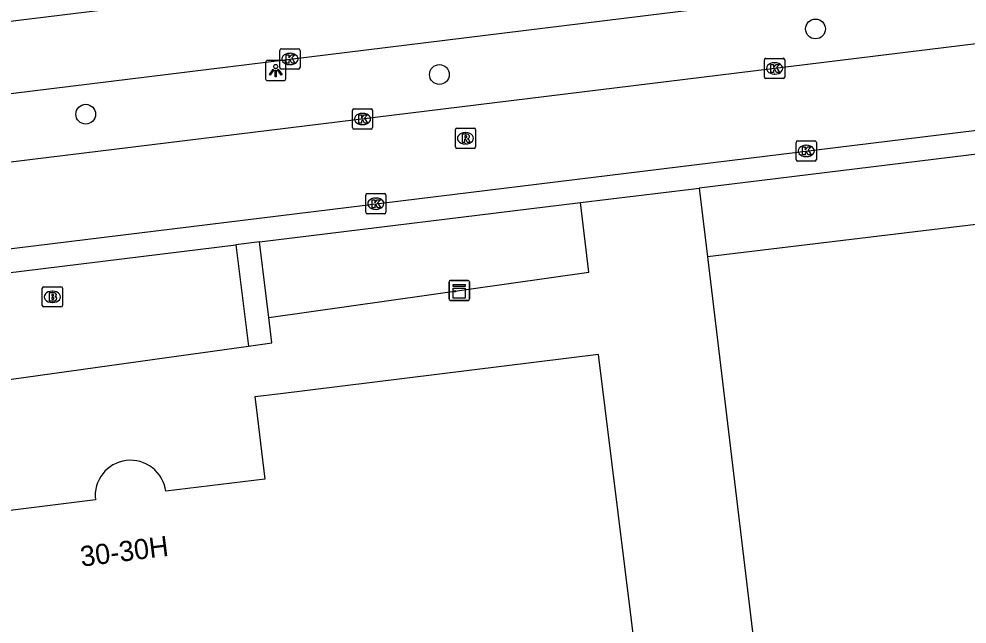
# Model space of a CAD drawing. Extents: x 161477 to 163040, y 383680 to 384868.
# Drawn here: x 162276.62 to 162323.55, y 384039.95 to 384069.9 of the extents above; entities that cross this region are included whole.
import ezdxf

# ---------------------------------------------------------------- set-up
doc = ezdxf.new("R2010")
doc.units = 0
for name, color, linetype in [('IMGEO_Boom', 7, 'Continuous'), ('IMGEO_Brandkraan', 7, 'Continuous'), ('IMGEO_Gemengd_bos', 7, 'Continuous'), ('IMGEO_Groenvoorziening', 7, 'Continuous'), ('IMGEO_Kast', 7, 'Continuous'), ('IMGEO_Kolk', 7, 'Continuous'), ('IMGEO_Lichtpunt', 7, 'Continuous'), ('IMGEO_Pand', 7, 'Continuous'), ('IMGEO_Pand_nummerreeks', 7, 'Continuous'), ('IMGEO_Rijbaan_lokaal_gesloten', 7, 'Continuous'), ('IMGEO_Rioolput', 7, 'Continuous'), ('IMGEO_Voetpad_open', 7, 'Continuous')]:
    doc.layers.add(name, color=color, linetype=linetype)

msp = doc.modelspace()

# ---------------------------------------------------------------- linework, layer by layer
at = {"layer": 'IMGEO_Boom'}
for centre in [(162316.049, 384069.409), (162297.434, 384067.152), (162279.927, 384065.187)]:
    msp.add_circle(centre, 0.489, dxfattribs=at)
at = {"layer": 'IMGEO_Brandkraan'}
for p, q in [((162277.776, 384055.718), (162277.776, 384056.57)), ((162277.851, 384056.644), (162278.703, 384056.644)), ((162278.777, 384056.57), (162278.777, 384055.718)), ((162278.264, 384056.424), (162278.289, 384056.424)), ((162278.703, 384055.644), (162277.851, 384055.644)), ((162278.287, 384055.864), (162278.262, 384055.864))]:
    msp.add_line(p, q, dxfattribs=at)
for points in [[(162277.776, 384055.718), (162277.776, 384056.57)], [(162277.851, 384056.644), (162278.703, 384056.644)], [(162278.777, 384056.57), (162278.777, 384055.718)], [(162278.124, 384056.344), (162278.124, 384055.944), (162278.337, 384055.944)], [(162278.355, 384056.344), (162278.124, 384056.344)], [(162278.303, 384056.263), (162278.249, 384056.263), (162278.249, 384056.187)], [(162278.249, 384056.187), (162278.302, 384056.187)], [(162278.311, 384056.111), (162278.249, 384056.111), (162278.249, 384056.03)], [(162278.249, 384056.03), (162278.311, 384056.03)], [(162278.703, 384055.644), (162277.851, 384055.644)]]:
    msp.add_lwpolyline(points, dxfattribs=at)
for centre, radius, start, end in [((162277.853, 384056.568), 0.0765, 91.552, 178.448), ((162277.853, 384056.568), 0.0765, 91.552, 178.448), ((162278.701, 384056.568), 0.0765, 1.552, 88.448), ((162278.701, 384056.568), 0.0765, 1.552, 88.448), ((162278.304, 384056.225), 0.0379, 267.8285, 90.9355), ((162278.312, 384056.07), 0.0404, 269.8759, 90.5077), ((162278.359, 384056.199), 0.145, 59.4692, 91.5367), ((162278.384, 384056.246), 0.0922, 285.5137, 58.1501), ((162278.389, 384056.054), 0.105, 301.3115, 78.989), ((162277.853, 384055.72), 0.0765, 181.552, 268.448), ((162277.853, 384055.72), 0.0765, 181.552, 268.448), ((162278.343, 384056.195), 0.251, 268.6676, 293.5347), ((162278.701, 384055.72), 0.0765, 271.552, 358.448), ((162278.701, 384055.72), 0.0765, 271.552, 358.448)]:
    msp.add_arc(centre, radius, start, end, dxfattribs=at)
for centre, major_axis, ratio, start_param, end_param in [((162278.263, 384056.144), (-0.387, 0.002), 0.722429, 4.712389, 7.853982), ((162278.288, 384056.144), (-0.39, 0.002), 0.717154, 1.570796, 4.712389)]:
    msp.add_ellipse(centre, major_axis=major_axis, ratio=ratio, start_param=start_param, end_param=end_param, dxfattribs=at)
at = {"layer": 'IMGEO_Gemengd_bos'}
for points in [[(162392.664, 384067.992), (162310.701, 384058.13)], [(162310.701, 384058.13), (162313.868, 384031.718), (162316.345, 384011.001), (162315.789, 384010.934)]]:
    msp.add_lwpolyline(points, dxfattribs=at)
at = {"layer": 'IMGEO_Groenvoorziening'}
for points in [[(162310.294, 384061.528), (162310.701, 384058.13)], [(162288.985, 384055.124), (162304.825, 384057.373), (162304.416, 384060.808)], [(162288.985, 384055.124), (162288.522, 384058.862)], [(162287.977, 384053.705), (162289.141, 384053.868), (162288.985, 384055.124)]]:
    msp.add_lwpolyline(points, dxfattribs=at)
at = {"layer": 'IMGEO_Kast'}
for p, q in [((162297.993, 384056.959), (162298.834, 384056.959)), ((162298.834, 384056.959), (162297.993, 384056.959)), ((162297.918, 384056.034), (162297.918, 384056.875)), ((162297.918, 384056.875), (162297.918, 384056.034)), ((162298.918, 384056.884), (162298.918, 384056.043)), ((162298.918, 384056.043), (162298.918, 384056.884)), ((162298.843, 384055.959), (162298.002, 384055.959)), ((162298.002, 384055.959), (162298.843, 384055.959))]:
    msp.add_line(p, q, dxfattribs=at)
for points in [[(162298.113, 384056.749), (162298.713, 384056.749), (162298.713, 384056.664), (162298.113, 384056.664), (162298.113, 384056.749)], [(162298.113, 384056.574), (162298.713, 384056.574), (162298.713, 384056.085), (162298.113, 384056.085), (162298.113, 384056.574)]]:
    msp.add_lwpolyline(points, dxfattribs=at)
msp.add_circle((162298.197, 384056.423), 0.0377, dxfattribs=at)
for centre, start, end in [((162297.996, 384056.881), 92.4484, 184.2845), ((162297.996, 384056.881), 92.4484, 184.2845), ((162298.84, 384056.881), 2.4484, 94.2845), ((162298.84, 384056.881), 2.4484, 94.2845), ((162297.996, 384056.037), 182.4484, 274.2845), ((162297.996, 384056.037), 182.4484, 274.2845), ((162298.84, 384056.037), 272.4484, 4.2845), ((162298.84, 384056.037), 272.4484, 4.2845)]:
    msp.add_arc(centre, 0.0779, start, end, dxfattribs=at)
at = {"layer": 'IMGEO_Kolk'}
for p, q in [((162289.535, 384067.495), (162289.535, 384068.347)), ((162289.61, 384068.421), (162290.462, 384068.421)), ((162290.023, 384068.201), (162290.048, 384068.201)), ((162290.536, 384068.347), (162290.536, 384067.495)), ((162313.522, 384067.027), (162313.522, 384067.879)), ((162313.597, 384067.953), (162314.449, 384067.953)), ((162314.01, 384067.733), (162314.035, 384067.733)), ((162314.523, 384067.879), (162314.523, 384067.027)), ((162290.462, 384067.421), (162289.61, 384067.421)), ((162290.046, 384067.641), (162290.021, 384067.641)), ((162314.449, 384066.953), (162313.597, 384066.953)), ((162314.033, 384067.173), (162314.008, 384067.173)), ((162293.128, 384064.523), (162293.128, 384065.375)), ((162293.203, 384065.449), (162294.055, 384065.449)), ((162294.129, 384065.375), (162294.129, 384064.523)), ((162293.616, 384065.229), (162293.641, 384065.229)), ((162294.055, 384064.449), (162293.203, 384064.449)), ((162293.639, 384064.669), (162293.614, 384064.669)), ((162315.089, 384062.942), (162315.089, 384063.794)), ((162315.164, 384063.868), (162316.016, 384063.868)), ((162315.577, 384063.648), (162315.602, 384063.648)), ((162316.09, 384063.794), (162316.09, 384062.942)), ((162315.6, 384063.088), (162315.575, 384063.088)), ((162316.016, 384062.868), (162315.164, 384062.868)), ((162293.785, 384060.329), (162293.785, 384061.181)), ((162293.86, 384061.255), (162294.712, 384061.255)), ((162294.786, 384061.181), (162294.786, 384060.329)), ((162294.273, 384061.035), (162294.298, 384061.035)), ((162294.712, 384060.255), (162293.86, 384060.255)), ((162294.296, 384060.475), (162294.271, 384060.475))]:
    msp.add_line(p, q, dxfattribs=at)
for points in [[(162289.535, 384067.495), (162289.535, 384068.347)], [(162289.61, 384068.421), (162290.462, 384068.421)], [(162290.536, 384068.347), (162290.536, 384067.495)], [(162289.856, 384068.121), (162289.979, 384068.121), (162289.979, 384067.97), (162290.109, 384068.121), (162290.273, 384068.121), (162290.127, 384067.97), (162290.28, 384067.721), (162290.128, 384067.721), (162290.043, 384067.885), (162289.979, 384067.818), (162289.979, 384067.721), (162289.856, 384067.721), (162289.856, 384068.121)], [(162313.522, 384067.027), (162313.522, 384067.879)], [(162313.597, 384067.953), (162314.449, 384067.953)], [(162314.523, 384067.879), (162314.523, 384067.027)], [(162290.462, 384067.421), (162289.61, 384067.421)], [(162313.843, 384067.653), (162313.966, 384067.653), (162313.966, 384067.502), (162314.096, 384067.653), (162314.26, 384067.653), (162314.114, 384067.502), (162314.267, 384067.253), (162314.115, 384067.253), (162314.03, 384067.417), (162313.966, 384067.35), (162313.966, 384067.253), (162313.843, 384067.253), (162313.843, 384067.653)], [(162314.449, 384066.953), (162313.597, 384066.953)], [(162293.128, 384064.523), (162293.128, 384065.375)], [(162293.203, 384065.449), (162294.055, 384065.449)], [(162294.129, 384065.375), (162294.129, 384064.523)], [(162293.449, 384065.149), (162293.572, 384065.149), (162293.572, 384064.998), (162293.702, 384065.149), (162293.866, 384065.149), (162293.72, 384064.998), (162293.873, 384064.749), (162293.721, 384064.749), (162293.636, 384064.913), (162293.572, 384064.846), (162293.572, 384064.749), (162293.449, 384064.749), (162293.449, 384065.149)], [(162294.055, 384064.449), (162293.203, 384064.449)], [(162315.089, 384062.942), (162315.089, 384063.794)], [(162315.164, 384063.868), (162316.016, 384063.868)], [(162315.41, 384063.568), (162315.533, 384063.568), (162315.533, 384063.417), (162315.663, 384063.568), (162315.827, 384063.568), (162315.681, 384063.417), (162315.834, 384063.168), (162315.682, 384063.168), (162315.597, 384063.332), (162315.533, 384063.265), (162315.533, 384063.168), (162315.41, 384063.168), (162315.41, 384063.568)], [(162316.09, 384063.794), (162316.09, 384062.942)], [(162316.016, 384062.868), (162315.164, 384062.868)], [(162293.785, 384060.329), (162293.785, 384061.181)], [(162293.86, 384061.255), (162294.712, 384061.255)], [(162294.786, 384061.181), (162294.786, 384060.329)], [(162294.106, 384060.955), (162294.229, 384060.955), (162294.229, 384060.804), (162294.359, 384060.955), (162294.523, 384060.955), (162294.377, 384060.804), (162294.53, 384060.555), (162294.378, 384060.555), (162294.293, 384060.719), (162294.229, 384060.652), (162294.229, 384060.555), (162294.106, 384060.555), (162294.106, 384060.955)], [(162294.712, 384060.255), (162293.86, 384060.255)]]:
    msp.add_lwpolyline(points, dxfattribs=at)
for centre, start, end in [((162289.612, 384068.345), 91.552, 178.448), ((162289.612, 384068.345), 91.552, 178.448), ((162290.46, 384068.345), 1.552, 88.448), ((162290.46, 384068.345), 1.552, 88.448), ((162313.599, 384067.877), 91.552, 178.448), ((162313.599, 384067.877), 91.552, 178.448), ((162314.447, 384067.877), 1.552, 88.448), ((162314.447, 384067.877), 1.552, 88.448), ((162289.612, 384067.497), 181.552, 268.448), ((162289.612, 384067.497), 181.552, 268.448), ((162290.46, 384067.497), 271.552, 358.448), ((162290.46, 384067.497), 271.552, 358.448), ((162313.599, 384067.029), 181.552, 268.448), ((162313.599, 384067.029), 181.552, 268.448), ((162314.447, 384067.029), 271.552, 358.448), ((162314.447, 384067.029), 271.552, 358.448), ((162293.205, 384065.373), 91.552, 178.448), ((162293.205, 384065.373), 91.552, 178.448), ((162294.053, 384065.373), 1.552, 88.448), ((162294.053, 384065.373), 1.552, 88.448), ((162293.205, 384064.525), 181.552, 268.448), ((162293.205, 384064.525), 181.552, 268.448), ((162294.053, 384064.525), 271.552, 358.448), ((162294.053, 384064.525), 271.552, 358.448), ((162315.166, 384063.792), 91.552, 178.448), ((162315.166, 384063.792), 91.552, 178.448), ((162316.014, 384063.792), 1.552, 88.448), ((162316.014, 384063.792), 1.552, 88.448), ((162315.166, 384062.944), 181.552, 268.448), ((162315.166, 384062.944), 181.552, 268.448), ((162316.014, 384062.944), 271.552, 358.448), ((162316.014, 384062.944), 271.552, 358.448), ((162293.862, 384061.179), 91.552, 178.448), ((162293.862, 384061.179), 91.552, 178.448), ((162294.71, 384061.179), 1.552, 88.448), ((162294.71, 384061.179), 1.552, 88.448), ((162293.862, 384060.331), 181.552, 268.448), ((162293.862, 384060.331), 181.552, 268.448), ((162294.71, 384060.331), 271.552, 358.448), ((162294.71, 384060.331), 271.552, 358.448)]:
    msp.add_arc(centre, 0.0765, start, end, dxfattribs=at)
for centre, major_axis, ratio, start_param, end_param in [((162290.022, 384067.921), (-0.387, 0.002), 0.722429, 4.712389, 7.853982), ((162290.047, 384067.921), (-0.39, 0.002), 0.717154, 1.570796, 4.712389), ((162314.009, 384067.453), (-0.387, 0.002), 0.722429, 4.712389, 7.853982), ((162314.034, 384067.453), (-0.39, 0.002), 0.717154, 1.570796, 4.712389), ((162293.615, 384064.949), (-0.387, 0.002), 0.722429, 4.712389, 7.853982), ((162293.64, 384064.949), (-0.39, 0.002), 0.717154, 1.570796, 4.712389), ((162315.576, 384063.368), (-0.387, 0.002), 0.722429, 4.712389, 7.853982), ((162315.601, 384063.368), (-0.39, 0.002), 0.717154, 1.570796, 4.712389), ((162294.272, 384060.755), (-0.387, 0.002), 0.722429, 4.712389, 7.853982), ((162294.297, 384060.755), (-0.39, 0.002), 0.717154, 1.570796, 4.712389)]:
    msp.add_ellipse(centre, major_axis=major_axis, ratio=ratio, start_param=start_param, end_param=end_param, dxfattribs=at)
at = {"layer": 'IMGEO_Lichtpunt'}
for p, q in [((162288.832, 384067.751), (162288.832, 384066.944)), ((162288.832, 384067.751), (162288.832, 384066.944)), ((162289.734, 384067.846), (162288.926, 384067.846)), ((162289.734, 384067.846), (162288.926, 384067.846)), ((162289.828, 384066.944), (162289.828, 384067.751)), ((162289.828, 384066.944), (162289.828, 384067.751)), ((162288.926, 384066.85), (162289.734, 384066.85)), ((162288.926, 384066.85), (162289.734, 384066.85))]:
    msp.add_line(p, q, dxfattribs=at)
for points in [[(162289.206, 384067.415), (162289.245, 384067.387), (162289.057, 384067.125), (162289.019, 384067.152), (162289.206, 384067.415)], [(162289.308, 384067.367), (162289.355, 384067.367), (162289.355, 384067.045), (162289.308, 384067.045), (162289.308, 384067.367)], [(162289.418, 384067.387), (162289.456, 384067.414), (162289.643, 384067.152), (162289.604, 384067.124), (162289.418, 384067.387)]]:
    msp.add_lwpolyline(points, dxfattribs=at)
msp.add_circle((162289.331, 384067.549), 0.0994, dxfattribs=at)
for centre, start, end in [((162288.926, 384067.751), 90, 180), ((162288.926, 384067.751), 90, 180), ((162289.734, 384067.751), 0, 90), ((162289.734, 384067.751), 0, 90), ((162288.926, 384066.944), 180, 270), ((162288.926, 384066.944), 180, 270), ((162289.734, 384066.944), 270, 0), ((162289.734, 384066.944), 270, 360)]:
    msp.add_arc(centre, 0.0946, start, end, dxfattribs=at)
at = {"layer": 'IMGEO_Pand'}
msp.add_lwpolyline([(162280.41, 384046.09), (162275.507, 384045.487), (162275.07, 384049.04), (162275.006, 384049.556), (162257.926, 384047.454), (162258.158, 384045.553), (162262.151, 384012.807), (162292.526, 384016.511), (162292.783, 384014.407), (162309.876, 384016.491), (162305.312, 384053.285), (162289.441, 384051.332), (162288.299, 384051.191), (162288.363, 384050.675), (162288.8, 384047.122), (162283.887, 384046.518)], dxfattribs=at)
msp.add_arc((162282.149, 384046.303), 1.752, 7.0357, 186.9993, dxfattribs=at)
at = {"layer": 'IMGEO_Rijbaan_lokaal_gesloten'}
for points in [[(162248.391, 384066.39), (162263.747, 384068.271), (162307.132, 384073.594), (162328.972, 384076.274), (162436.622, 384089.378), (162523.472, 384100.182), (162541.672, 384102.783), (162554.672, 384105.134), (162566.872, 384107.635), (162574.422, 384109.336), (162609.421, 384117.982)], [(162609.236, 384114.248), (162604.892, 384113.129), (162598.182, 384111.443), (162583.97, 384107.926), (162563.733, 384103.254), (162553.921, 384101.256), (162534.962, 384097.975), (162500, 384093.468), (162481.264, 384091.095), (162457.811, 384088.372), (162442.901, 384086.436), (162402.758, 384081.663), (162381.895, 384078.899), (162368.059, 384077.415), (162337.394, 384073.713), (162307.499, 384070.04), (162248.941, 384062.845)], [(162517.624, 384092.325), (162395.867, 384077.5), (162260.044, 384060.826)], [(162261.855, 384056.776), (162395.494, 384073.171), (162405.589, 384074.388), (162472.495, 384082.536)]]:
    msp.add_lwpolyline(points, dxfattribs=at)
at = {"layer": 'IMGEO_Rioolput'}
for p, q in [((162298.298, 384064.496), (162299.15, 384064.496)), ((162298.223, 384063.57), (162298.223, 384064.422)), ((162298.711, 384064.276), (162298.736, 384064.276)), ((162299.224, 384064.422), (162299.224, 384063.57)), ((162298.734, 384063.716), (162298.709, 384063.716)), ((162299.15, 384063.496), (162298.298, 384063.496))]:
    msp.add_line(p, q, dxfattribs=at)
for points in [[(162298.298, 384064.496), (162299.15, 384064.496)], [(162298.223, 384063.57), (162298.223, 384064.422)], [(162298.812, 384064.194), (162298.56, 384064.196), (162298.56, 384063.796)], [(162298.738, 384064.115), (162298.684, 384064.115), (162298.684, 384064.034)], [(162298.684, 384064.034), (162298.736, 384064.034)], [(162299.224, 384064.422), (162299.224, 384063.57)], [(162298.56, 384063.796), (162298.684, 384063.796), (162298.684, 384063.958), (162298.695, 384063.958)], [(162298.742, 384063.929), (162298.813, 384063.796), (162298.953, 384063.796), (162298.888, 384063.922)], [(162299.15, 384063.496), (162298.298, 384063.496)]]:
    msp.add_lwpolyline(points, dxfattribs=at)
for centre, radius, start, end in [((162298.3, 384064.42), 0.0765, 91.552, 178.448), ((162298.3, 384064.42), 0.0765, 91.552, 178.448), ((162299.148, 384064.42), 0.0765, 1.552, 88.448), ((162299.148, 384064.42), 0.0765, 1.552, 88.448), ((162298.72, 384064.223), 0.19, 274.7715, 282.9687), ((162298.744, 384064.019), 0.0964, 77.0061, 93.1865), ((162298.758, 384064.076), 0.0378, 276.6634, 79.6772), ((162298.811, 384064.084), 0.109, 350.3612, 89.416), ((162298.809, 384064.084), 0.112, 277.5842, 350.9817), ((162298.793, 384063.869), 0.108, 29.5134, 73.7905), ((162298.3, 384063.572), 0.0765, 181.552, 268.448), ((162298.3, 384063.572), 0.0765, 181.552, 268.448), ((162298.694, 384063.905), 0.0533, 26.0293, 88.6989), ((162299.148, 384063.572), 0.0765, 271.552, 358.448), ((162299.148, 384063.572), 0.0765, 271.552, 358.448)]:
    msp.add_arc(centre, radius, start, end, dxfattribs=at)
for centre, major_axis, ratio, start_param, end_param in [((162298.71, 384063.996), (-0.387, 0.002), 0.722429, 4.712389, 7.853982), ((162298.735, 384063.996), (-0.39, 0.002), 0.717154, 1.570796, 4.712389)]:
    msp.add_ellipse(centre, major_axis=major_axis, ratio=ratio, start_param=start_param, end_param=end_param, dxfattribs=at)
at = {"layer": 'IMGEO_Voetpad_open'}
for points in [[(162354.651, 384066.958), (162310.294, 384061.528)], [(162304.416, 384060.808), (162309.894, 384061.479), (162310.294, 384061.528)], [(162288.522, 384058.862), (162304.416, 384060.808)], [(162288.522, 384058.862), (162287.358, 384058.72)], [(162274.037, 384057.089), (162287.358, 384058.72)], [(162287.358, 384058.72), (162287.977, 384053.705)], [(162274.705, 384051.849), (162283.349, 384053.058), (162287.977, 384053.705)]]:
    msp.add_lwpolyline(points, dxfattribs=at)

# ---------------------------------------------------------------- texts
at = {"layer": 'IMGEO_Pand_nummerreeks'}
msp.add_text('30-30H', height=1, rotation=7.1271, dxfattribs=at).set_placement((162279.72, 384042.784))

doc.saveas('drawing.dxf')
